// Mitsubishi GX Works2 project: 37.锯床一键暂停（跳转指令）   PLC: FX3U/FX3UC

PROGRAM MAIN
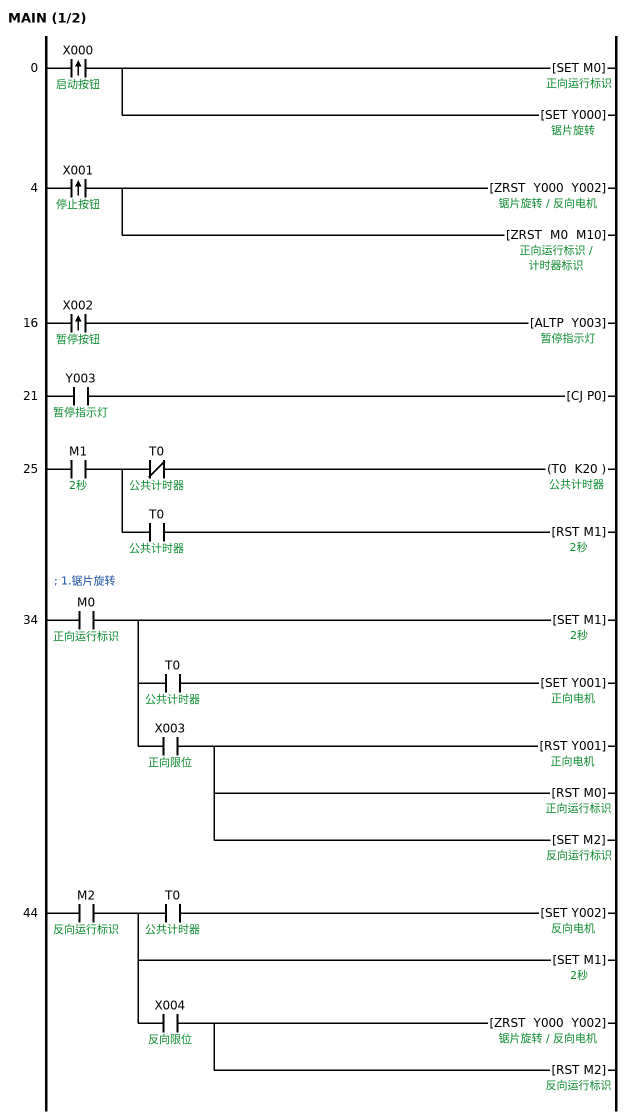
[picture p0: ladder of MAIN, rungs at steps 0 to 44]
0     LDP     X000  ; 启动按钮
      SET     M0  ; 正向运行标识
      SET     Y000  ; 锯片旋转
4     LDP     X001  ; 停止按钮
      ZRST    Y000 Y002  ; 反向电机
      ZRST    M0 M10  ; 计时器标识
16    LDP     X002  ; 暂停按钮
      ALTP    Y003  ; 暂停指示灯
21    LD      Y003  ; 暂停指示灯
      CJ      P0
25    LD      M1  ; 2秒
      MPS
      ANI     T0  ; 公共计时器
      OUT     T0 K20  ; 公共计时器
      MPP
      AND     T0  ; 公共计时器
      RST     M1  ; 2秒
; 1.锯片旋转
34    LD      M0  ; 正向运行标识
      SET     M1  ; 2秒
      MPS
      AND     T0  ; 公共计时器
      SET     Y001  ; 正向电机
      MPP
      AND     X003  ; 正向限位
      RST     Y001  ; 正向电机
      RST     M0  ; 正向运行标识
      SET     M2  ; 反向运行标识
44    LD      M2  ; 反向运行标识
      MPS
      AND     T0  ; 公共计时器
      SET     Y002  ; 反向电机
      MPP
      SET     M1  ; 2秒
      AND     X004  ; 反向限位
      ZRST    Y000 Y002
      RST     M2  ; 反向运行标识
      P0
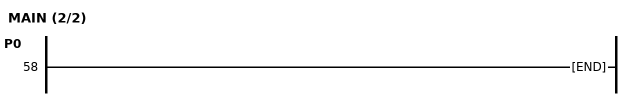
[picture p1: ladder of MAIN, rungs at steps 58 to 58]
58    END
END_PROGRAM

// device comments not shown above
M3  ; 暂停标识
S0  ; 暂停标识
P1  ; 第二步：正向到位
P2  ; 反向到位
